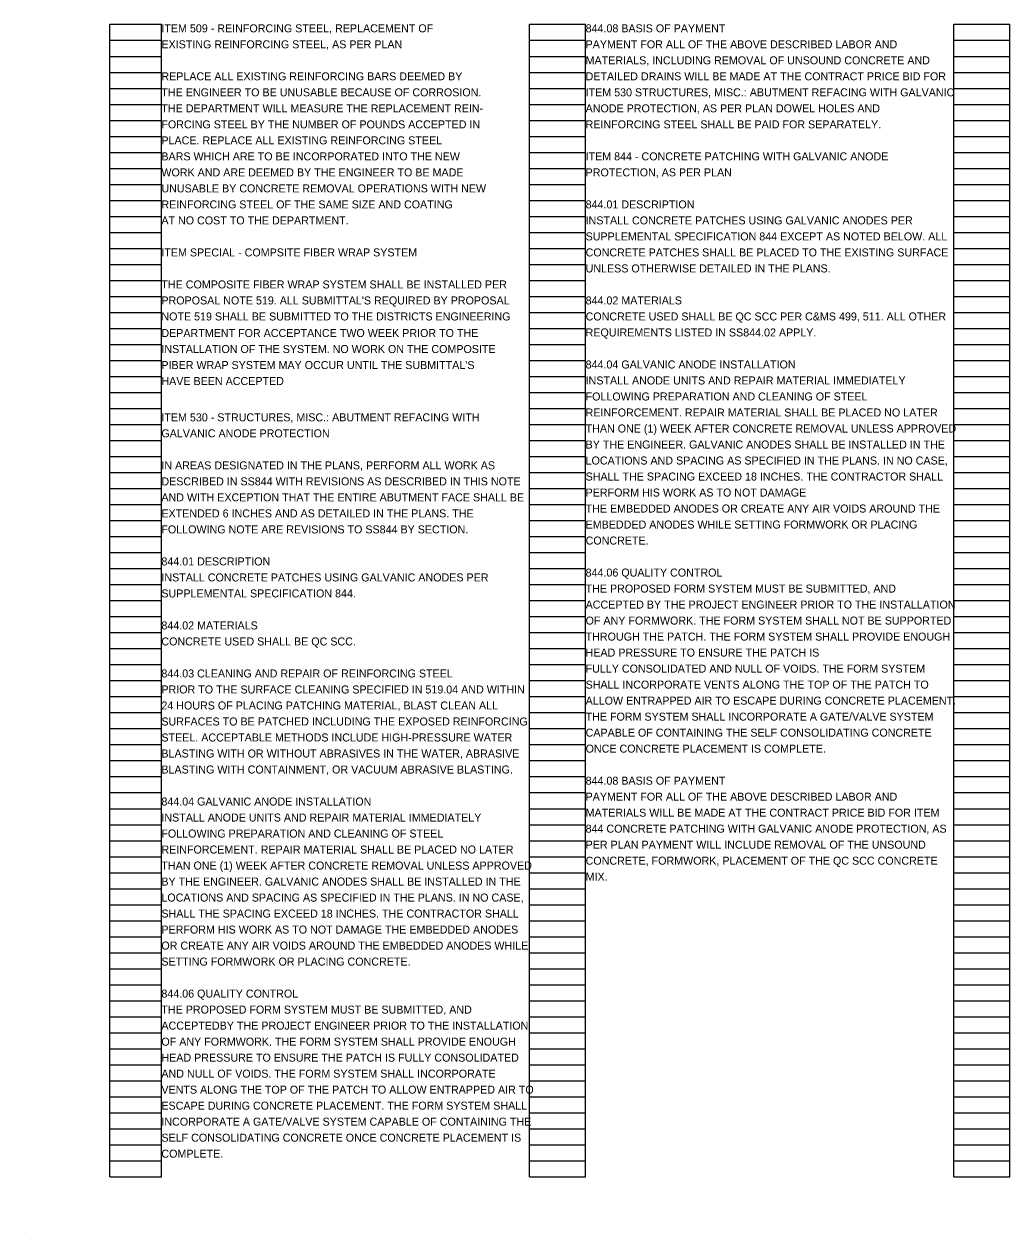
# Model space of a CAD drawing. Extents: x 0 to 36.6, y -0.1 to 44.
# Drawn here: x 0 to 17.24, y 22.84 to 43.99 of the extents above; entities that cross this region are included whole.
import ezdxf

# ---------------------------------------------------------------- set-up
doc = ezdxf.new("R2010")
doc.units = 0
doc.layers.add('SH_Data', color=7, linetype='Continuous')
doc.layers.add('SH_Text', color=7, linetype='Continuous')

msp = doc.modelspace()

# ---------------------------------------------------------------- linework, layer by layer
at = {"layer": 'SH_Data'}
for p, q in [((1.5, 23.824), (1.5, 43.984)), ((1.5, 43.984), (2.4, 43.984)), ((2.4, 23.824), (2.4, 43.984)), ((8.84, 23.824), (8.84, 43.984)), ((8.84, 43.984), (9.82, 43.984)), ((9.82, 23.824), (9.82, 43.984)), ((16.26, 23.824), (16.26, 43.984)), ((16.26, 43.984), (17.24, 43.984)), ((17.24, 23.824), (17.24, 43.984)), ((1.5, 43.704), (2.4, 43.704)), ((8.84, 43.704), (9.82, 43.704)), ((16.26, 43.704), (17.24, 43.704)), ((1.5, 43.424), (2.4, 43.424)), ((8.84, 43.424), (9.82, 43.424)), ((16.26, 43.424), (17.24, 43.424)), ((1.5, 43.144), (2.4, 43.144)), ((8.84, 43.144), (9.82, 43.144)), ((16.26, 43.144), (17.24, 43.144)), ((1.5, 42.864), (2.4, 42.864)), ((8.84, 42.864), (9.82, 42.864)), ((16.26, 42.864), (17.24, 42.864)), ((1.5, 42.584), (2.4, 42.584)), ((8.84, 42.584), (9.82, 42.584)), ((16.26, 42.584), (17.24, 42.584)), ((1.5, 42.304), (2.4, 42.304)), ((8.84, 42.304), (9.82, 42.304)), ((16.26, 42.304), (17.24, 42.304)), ((1.5, 42.024), (2.4, 42.024)), ((8.84, 42.024), (9.82, 42.024)), ((16.26, 42.024), (17.24, 42.024)), ((1.5, 41.744), (2.4, 41.744)), ((8.84, 41.744), (9.82, 41.744)), ((16.26, 41.744), (17.24, 41.744)), ((1.5, 41.464), (2.4, 41.464)), ((8.84, 41.464), (9.82, 41.464)), ((16.26, 41.464), (17.24, 41.464)), ((1.5, 41.184), (2.4, 41.184)), ((8.84, 41.184), (9.82, 41.184)), ((16.26, 41.184), (17.24, 41.184)), ((1.5, 40.904), (2.4, 40.904)), ((8.84, 40.904), (9.82, 40.904)), ((16.26, 40.904), (17.24, 40.904)), ((1.5, 40.624), (2.4, 40.624)), ((8.84, 40.624), (9.82, 40.624)), ((16.26, 40.624), (17.24, 40.624)), ((1.5, 40.344), (2.4, 40.344)), ((8.84, 40.344), (9.82, 40.344)), ((16.26, 40.344), (17.24, 40.344)), ((1.5, 40.064), (2.4, 40.064)), ((8.84, 40.064), (9.82, 40.064)), ((16.26, 40.064), (17.24, 40.064)), ((1.5, 39.784), (2.4, 39.784)), ((8.84, 39.784), (9.82, 39.784)), ((16.26, 39.784), (17.24, 39.784)), ((1.5, 39.504), (2.4, 39.504)), ((8.84, 39.504), (9.82, 39.504)), ((16.26, 39.504), (17.24, 39.504)), ((1.5, 39.224), (2.4, 39.224)), ((8.84, 39.224), (9.82, 39.224)), ((16.26, 39.224), (17.24, 39.224)), ((1.5, 38.944), (2.4, 38.944)), ((8.84, 38.944), (9.82, 38.944)), ((16.26, 38.944), (17.24, 38.944)), ((1.5, 38.664), (2.4, 38.664)), ((8.84, 38.664), (9.82, 38.664)), ((16.26, 38.664), (17.24, 38.664)), ((1.5, 38.384), (2.4, 38.384)), ((8.84, 38.384), (9.82, 38.384)), ((16.26, 38.384), (17.24, 38.384)), ((1.5, 38.104), (2.4, 38.104)), ((8.84, 38.104), (9.82, 38.104)), ((16.26, 38.104), (17.24, 38.104)), ((1.5, 37.824), (2.4, 37.824)), ((8.84, 37.824), (9.82, 37.824)), ((16.26, 37.824), (17.24, 37.824)), ((1.5, 37.544), (2.4, 37.544)), ((8.84, 37.544), (9.82, 37.544)), ((16.26, 37.544), (17.24, 37.544)), ((1.5, 37.264), (2.4, 37.264)), ((8.84, 37.264), (9.82, 37.264)), ((16.26, 37.264), (17.24, 37.264)), ((1.5, 36.984), (2.4, 36.984)), ((8.84, 36.984), (9.82, 36.984)), ((16.26, 36.984), (17.24, 36.984)), ((1.5, 36.704), (2.4, 36.704)), ((8.84, 36.704), (9.82, 36.704)), ((16.26, 36.704), (17.24, 36.704)), ((1.5, 36.424), (2.4, 36.424)), ((8.84, 36.424), (9.82, 36.424)), ((16.26, 36.424), (17.24, 36.424)), ((1.5, 36.144), (2.4, 36.144)), ((8.84, 36.144), (9.82, 36.144)), ((16.26, 36.144), (17.24, 36.144)), ((1.5, 35.864), (2.4, 35.864)), ((8.84, 35.864), (9.82, 35.864)), ((16.26, 35.864), (17.24, 35.864)), ((1.5, 35.584), (2.4, 35.584)), ((8.84, 35.584), (9.82, 35.584)), ((16.26, 35.584), (17.24, 35.584)), ((1.5, 35.304), (2.4, 35.304)), ((8.84, 35.304), (9.82, 35.304)), ((16.26, 35.304), (17.24, 35.304)), ((1.5, 35.024), (2.4, 35.024)), ((8.84, 35.024), (9.82, 35.024)), ((16.26, 35.024), (17.24, 35.024)), ((1.5, 34.744), (2.4, 34.744)), ((8.84, 34.744), (9.82, 34.744)), ((16.26, 34.744), (17.24, 34.744)), ((1.5, 34.464), (2.4, 34.464)), ((8.84, 34.464), (9.82, 34.464)), ((16.26, 34.464), (17.24, 34.464)), ((1.5, 34.184), (2.4, 34.184)), ((8.84, 34.184), (9.82, 34.184)), ((16.26, 34.184), (17.24, 34.184)), ((1.5, 33.904), (2.4, 33.904)), ((8.84, 33.904), (9.82, 33.904)), ((16.26, 33.904), (17.24, 33.904)), ((1.5, 33.624), (2.4, 33.624)), ((8.84, 33.624), (9.82, 33.624)), ((16.26, 33.624), (17.24, 33.624)), ((1.5, 33.344), (2.4, 33.344)), ((8.84, 33.344), (9.82, 33.344)), ((16.26, 33.344), (17.24, 33.344)), ((1.5, 33.064), (2.4, 33.064)), ((8.84, 33.064), (9.82, 33.064)), ((16.26, 33.064), (17.24, 33.064)), ((1.5, 32.784), (2.4, 32.784)), ((8.84, 32.784), (9.82, 32.784)), ((16.26, 32.784), (17.24, 32.784)), ((1.5, 32.504), (2.4, 32.504)), ((8.84, 32.504), (9.82, 32.504)), ((16.26, 32.504), (17.24, 32.504)), ((1.5, 32.224), (2.4, 32.224)), ((8.84, 32.224), (9.82, 32.224)), ((16.26, 32.224), (17.24, 32.224)), ((1.5, 31.944), (2.4, 31.944)), ((8.84, 31.944), (9.82, 31.944)), ((16.26, 31.944), (17.24, 31.944)), ((1.5, 31.664), (2.4, 31.664)), ((8.84, 31.664), (9.82, 31.664)), ((16.26, 31.664), (17.24, 31.664)), ((1.5, 31.384), (2.4, 31.384)), ((8.84, 31.384), (9.82, 31.384)), ((16.26, 31.384), (17.24, 31.384)), ((1.5, 31.104), (2.4, 31.104)), ((8.84, 31.104), (9.82, 31.104)), ((16.26, 31.104), (17.24, 31.104)), ((1.5, 30.824), (2.4, 30.824)), ((8.84, 30.824), (9.82, 30.824)), ((16.26, 30.824), (17.24, 30.824)), ((1.5, 30.544), (2.4, 30.544)), ((8.84, 30.544), (9.82, 30.544)), ((16.26, 30.544), (17.24, 30.544)), ((1.5, 30.264), (2.4, 30.264)), ((8.84, 30.264), (9.82, 30.264)), ((16.26, 30.264), (17.24, 30.264)), ((1.5, 29.984), (2.4, 29.984)), ((8.84, 29.984), (9.82, 29.984)), ((16.26, 29.984), (17.24, 29.984)), ((1.5, 29.704), (2.4, 29.704)), ((8.84, 29.704), (9.82, 29.704)), ((16.26, 29.704), (17.24, 29.704)), ((1.5, 29.424), (2.4, 29.424)), ((8.84, 29.424), (9.82, 29.424)), ((16.26, 29.424), (17.24, 29.424)), ((1.5, 29.144), (2.4, 29.144)), ((8.84, 29.144), (9.82, 29.144)), ((16.26, 29.144), (17.24, 29.144)), ((1.5, 28.864), (2.4, 28.864)), ((8.84, 28.864), (9.82, 28.864)), ((16.26, 28.864), (17.24, 28.864)), ((1.5, 28.584), (2.4, 28.584)), ((8.84, 28.584), (9.82, 28.584)), ((16.26, 28.584), (17.24, 28.584)), ((1.5, 28.304), (2.4, 28.304)), ((8.84, 28.304), (9.82, 28.304)), ((16.26, 28.304), (17.24, 28.304)), ((1.5, 28.024), (2.4, 28.024)), ((8.84, 28.024), (9.82, 28.024)), ((16.26, 28.024), (17.24, 28.024)), ((1.5, 27.744), (2.4, 27.744)), ((8.84, 27.744), (9.82, 27.744)), ((16.26, 27.744), (17.24, 27.744)), ((1.5, 27.464), (2.4, 27.464)), ((8.84, 27.464), (9.82, 27.464)), ((16.26, 27.464), (17.24, 27.464)), ((1.5, 27.184), (2.4, 27.184)), ((8.84, 27.184), (9.82, 27.184)), ((16.26, 27.184), (17.24, 27.184)), ((1.5, 26.904), (2.4, 26.904)), ((8.84, 26.904), (9.82, 26.904)), ((16.26, 26.904), (17.24, 26.904)), ((1.5, 26.624), (2.4, 26.624)), ((8.84, 26.624), (9.82, 26.624)), ((16.26, 26.624), (17.24, 26.624)), ((1.5, 26.344), (2.4, 26.344)), ((8.84, 26.344), (9.82, 26.344)), ((16.26, 26.344), (17.24, 26.344)), ((1.5, 26.064), (2.4, 26.064)), ((8.84, 26.064), (9.82, 26.064)), ((16.26, 26.064), (17.24, 26.064)), ((1.5, 25.784), (2.4, 25.784)), ((8.84, 25.784), (9.82, 25.784)), ((16.26, 25.784), (17.24, 25.784)), ((1.5, 25.504), (2.4, 25.504)), ((8.84, 25.504), (9.82, 25.504)), ((16.26, 25.504), (17.24, 25.504)), ((1.5, 25.224), (2.4, 25.224)), ((8.84, 25.224), (9.82, 25.224)), ((16.26, 25.224), (17.24, 25.224)), ((1.5, 24.944), (2.4, 24.944)), ((8.84, 24.944), (9.82, 24.944)), ((16.26, 24.944), (17.24, 24.944)), ((1.5, 24.664), (2.4, 24.664)), ((8.84, 24.664), (9.82, 24.664)), ((16.26, 24.664), (17.24, 24.664)), ((1.5, 24.384), (2.4, 24.384)), ((8.84, 24.384), (9.82, 24.384)), ((16.26, 24.384), (17.24, 24.384)), ((1.5, 24.104), (2.4, 24.104)), ((8.84, 24.104), (9.82, 24.104)), ((16.26, 24.104), (17.24, 24.104)), ((1.5, 23.824), (2.4, 23.824)), ((8.84, 23.824), (9.82, 23.824)), ((16.26, 23.824), (17.24, 23.824)), ((0, 22.844), (0, 22.844))]:
    msp.add_line(p, q, dxfattribs=at)

# ---------------------------------------------------------------- texts
at = {"layer": 'SH_Text'}
for s, p in [('ITEM 509 - REINFORCING STEEL, REPLACEMENT OF', (2.4, 43.844)), ('844.08 BASIS OF PAYMENT', (9.82, 43.844)), ('EXISTING REINFORCING STEEL, AS PER PLAN', (2.4, 43.564)), ('PAYMENT FOR ALL OF THE ABOVE DESCRIBED LABOR AND', (9.82, 43.564)), ('MATERIALS, INCLUDING REMOVAL OF UNSOUND CONCRETE AND', (9.82, 43.284)), ('REPLACE ALL EXISTING REINFORCING BARS DEEMED BY', (2.4, 43.004)), ('DETAILED DRAINS WILL BE MADE AT THE CONTRACT PRICE BID FOR', (9.82, 43.004)), ('THE ENGINEER TO BE UNUSABLE BECAUSE OF CORROSION.', (2.4, 42.724)), ('ITEM 530 STRUCTURES, MISC.: ABUTMENT REFACING WITH GALVANIC', (9.82, 42.724)), ('THE DEPARTMENT WILL MEASURE THE REPLACEMENT REIN-', (2.4, 42.444)), ('ANODE PROTECTION, AS PER PLAN DOWEL HOLES AND', (9.82, 42.444)), ('FORCING STEEL BY THE NUMBER OF POUNDS ACCEPTED IN', (2.4, 42.164)), ('REINFORCING STEEL SHALL BE PAID FOR SEPARATELY.', (9.82, 42.164)), ('PLACE. REPLACE ALL EXISTING REINFORCING STEEL', (2.4, 41.884)), ('BARS WHICH ARE TO BE INCORPORATED INTO THE NEW', (2.4, 41.604)), ('ITEM 844 - CONCRETE PATCHING WITH GALVANIC ANODE', (9.82, 41.604)), ('WORK AND ARE DEEMED BY THE ENGINEER TO BE MADE', (2.4, 41.324)), ('PROTECTION, AS PER PLAN', (9.82, 41.324)), ('UNUSABLE BY CONCRETE REMOVAL OPERATIONS WITH NEW', (2.4, 41.044)), ('REINFORCING STEEL OF THE SAME SIZE AND COATING', (2.4, 40.764)), ('844.01 DESCRIPTION', (9.82, 40.764)), ('AT NO COST TO THE DEPARTMENT.', (2.4, 40.484)), ('INSTALL CONCRETE PATCHES USING GALVANIC ANODES PER', (9.82, 40.484)), ('SUPPLEMENTAL SPECIFICATION 844 EXCEPT AS NOTED BELOW. ALL', (9.82, 40.204)), ('ITEM SPECIAL - COMPSITE FIBER WRAP SYSTEM', (2.4, 39.924)), ('CONCRETE PATCHES SHALL BE PLACED TO THE EXISTING SURFACE', (9.82, 39.924)), ('UNLESS OTHERWISE DETAILED IN THE PLANS.', (9.82, 39.644)), ('THE COMPOSITE FIBER WRAP SYSTEM SHALL BE INSTALLED PER', (2.4, 39.364)), ("PROPOSAL NOTE 519. ALL SUBMITTAL'S REQUIRED BY PROPOSAL", (2.4, 39.084)), ('844.02 MATERIALS', (9.82, 39.084)), ('NOTE 519 SHALL BE SUBMITTED TO THE DISTRICTS ENGINEERING', (2.4, 38.804)), ('CONCRETE USED SHALL BE QC SCC PER C&MS 499, 511. ALL OTHER', (9.82, 38.804)), ('DEPARTMENT FOR ACCEPTANCE TWO WEEK PRIOR TO THE', (2.4, 38.514)), ('REQUIREMENTS LISTED IN SS844.02 APPLY.', (9.82, 38.524)), ('INSTALLATION OF THE SYSTEM. NO WORK ON THE COMPOSITE', (2.4, 38.234)), ("PIBER WRAP SYSTEM MAY OCCUR UNTIL THE SUBMITTAL'S", (2.4, 37.954)), ('844.04 GALVANIC ANODE INSTALLATION', (9.82, 37.964)), ('HAVE BEEN ACCEPTED', (2.4, 37.674)), ('INSTALL ANODE UNITS AND REPAIR MATERIAL IMMEDIATELY', (9.82, 37.684)), ('FOLLOWING PREPARATION AND CLEANING OF STEEL', (9.82, 37.404)), ('REINFORCEMENT. REPAIR MATERIAL SHALL BE PLACED NO LATER', (9.82, 37.124)), ('ITEM 530 - STRUCTURES, MISC.: ABUTMENT REFACING WITH', (2.4, 37.039)), ('GALVANIC ANODE PROTECTION', (2.4, 36.759)), ('THAN ONE (1) WEEK AFTER CONCRETE REMOVAL UNLESS APPROVED', (9.82, 36.844)), ('BY THE ENGINEER. GALVANIC ANODES SHALL BE INSTALLED IN THE', (9.82, 36.564)), ('LOCATIONS AND SPACING AS SPECIFIED IN THE PLANS. IN NO CASE,', (9.82, 36.284)), ('IN AREAS DESIGNATED IN THE PLANS, PERFORM ALL WORK AS', (2.4, 36.199)), ('DESCRIBED IN SS844 WITH REVISIONS AS DESCRIBED IN THIS NOTE', (2.4, 35.919)), ('SHALL THE SPACING EXCEED 18 INCHES. THE CONTRACTOR SHALL', (9.82, 36.004)), ('AND WITH EXCEPTION THAT THE ENTIRE ABUTMENT FACE SHALL BE', (2.4, 35.639)), ('PERFORM HIS WORK AS TO NOT DAMAGE', (9.82, 35.724)), ('THE EMBEDDED ANODES OR CREATE ANY AIR VOIDS AROUND THE', (9.82, 35.444)), ('EXTENDED 6 INCHES AND AS DETAILED IN THE PLANS. THE', (2.4, 35.359)), ('FOLLOWING NOTE ARE REVISIONS TO SS844 BY SECTION.', (2.4, 35.079)), ('EMBEDDED ANODES WHILE SETTING FORMWORK OR PLACING', (9.82, 35.164)), ('CONCRETE.', (9.82, 34.884)), ('844.01 DESCRIPTION', (2.4, 34.519)), ('844.06 QUALITY CONTROL', (9.82, 34.324)), ('INSTALL CONCRETE PATCHES USING GALVANIC ANODES PER', (2.4, 34.239)), ('SUPPLEMENTAL SPECIFICATION 844.', (2.4, 33.959)), ('THE PROPOSED FORM SYSTEM MUST BE SUBMITTED, AND', (9.82, 34.044)), ('ACCEPTED BY THE PROJECT ENGINEER PRIOR TO THE INSTALLATION', (9.82, 33.764)), ('OF ANY FORMWORK. THE FORM SYSTEM SHALL NOT BE SUPPORTED', (9.82, 33.484)), ('844.02 MATERIALS', (2.4, 33.399)), ('CONCRETE USED SHALL BE QC SCC.', (2.4, 33.119)), ('THROUGH THE PATCH. THE FORM SYSTEM SHALL PROVIDE ENOUGH', (9.82, 33.204)), ('HEAD PRESSURE TO ENSURE THE PATCH IS', (9.82, 32.924)), ('FULLY CONSOLIDATED AND NULL OF VOIDS. THE FORM SYSTEM', (9.82, 32.644)), ('844.03 CLEANING AND REPAIR OF REINFORCING STEEL', (2.4, 32.559)), ('PRIOR TO THE SURFACE CLEANING SPECIFIED IN 519.04 AND WITHIN', (2.4, 32.279)), ('SHALL INCORPORATE VENTS ALONG THE TOP OF THE PATCH TO', (9.82, 32.364)), ('24 HOURS OF PLACING PATCHING MATERIAL, BLAST CLEAN ALL', (2.4, 31.999)), ('ALLOW ENTRAPPED AIR TO ESCAPE DURING CONCRETE PLACEMENT.', (9.82, 32.084)), ('THE FORM SYSTEM SHALL INCORPORATE A GATE/VALVE SYSTEM', (9.82, 31.804)), ('SURFACES TO BE PATCHED INCLUDING THE EXPOSED REINFORCING', (2.4, 31.719)), ('STEEL. ACCEPTABLE METHODS INCLUDE HIGH-PRESSURE WATER', (2.4, 31.439)), ('CAPABLE OF CONTAINING THE SELF CONSOLIDATING CONCRETE', (9.82, 31.524)), ('BLASTING WITH OR WITHOUT ABRASIVES IN THE WATER, ABRASIVE', (2.4, 31.159)), ('ONCE CONCRETE PLACEMENT IS COMPLETE.', (9.82, 31.244)), ('BLASTING WITH CONTAINMENT, OR VACUUM ABRASIVE BLASTING.', (2.4, 30.879)), ('844.08 BASIS OF PAYMENT', (9.82, 30.684)), ('844.04 GALVANIC ANODE INSTALLATION', (2.4, 30.319)), ('PAYMENT FOR ALL OF THE ABOVE DESCRIBED LABOR AND', (9.82, 30.404)), ('MATERIALS WILL BE MADE AT THE CONTRACT PRICE BID FOR ITEM', (9.82, 30.124)), ('INSTALL ANODE UNITS AND REPAIR MATERIAL IMMEDIATELY', (2.4, 30.039)), ('FOLLOWING PREPARATION AND CLEANING OF STEEL', (2.4, 29.759)), ('844 CONCRETE PATCHING WITH GALVANIC ANODE PROTECTION, AS', (9.82, 29.844)), ('REINFORCEMENT. REPAIR MATERIAL SHALL BE PLACED NO LATER', (2.4, 29.479)), ('PER PLAN PAYMENT WILL INCLUDE REMOVAL OF THE UNSOUND', (9.82, 29.564)), ('CONCRETE, FORMWORK, PLACEMENT OF THE QC SCC CONCRETE', (9.82, 29.284)), ('THAN ONE (1) WEEK AFTER CONCRETE REMOVAL UNLESS APPROVED', (2.4, 29.199)), ('BY THE ENGINEER. GALVANIC ANODES SHALL BE INSTALLED IN THE', (2.4, 28.919)), ('MIX.', (9.82, 29.004)), ('LOCATIONS AND SPACING AS SPECIFIED IN THE PLANS. IN NO CASE,', (2.4, 28.639)), ('SHALL THE SPACING EXCEED 18 INCHES. THE CONTRACTOR SHALL', (2.4, 28.359)), ('PERFORM HIS WORK AS TO NOT DAMAGE THE EMBEDDED ANODES', (2.4, 28.079)), ('OR CREATE ANY AIR VOIDS AROUND THE EMBEDDED ANODES WHILE', (2.4, 27.799)), ('SETTING FORMWORK OR PLACING CONCRETE.', (2.4, 27.519)), ('844.06 QUALITY CONTROL', (2.4, 26.959)), ('THE PROPOSED FORM SYSTEM MUST BE SUBMITTED, AND', (2.4, 26.679)), ('ACCEPTEDBY THE PROJECT ENGINEER PRIOR TO THE INSTALLATION', (2.4, 26.399)), ('OF ANY FORMWORK. THE FORM SYSTEM SHALL PROVIDE ENOUGH', (2.4, 26.119)), ('HEAD PRESSURE TO ENSURE THE PATCH IS FULLY CONSOLIDATED', (2.4, 25.839)), ('AND NULL OF VOIDS. THE FORM SYSTEM SHALL INCORPORATE', (2.4, 25.559)), ('VENTS ALONG THE TOP OF THE PATCH TO ALLOW ENTRAPPED AIR TO', (2.4, 25.279)), ('ESCAPE DURING CONCRETE PLACEMENT. THE FORM SYSTEM SHALL', (2.4, 24.999)), ('INCORPORATE A GATE/VALVE SYSTEM CAPABLE OF CONTAINING THE', (2.4, 24.719)), ('SELF CONSOLIDATING CONCRETE ONCE CONCRETE PLACEMENT IS', (2.4, 24.439)), ('COMPLETE.', (2.4, 24.159))]:
    msp.add_text(s, height=0.14, dxfattribs=at).set_placement(p)

doc.saveas('drawing.dxf')
